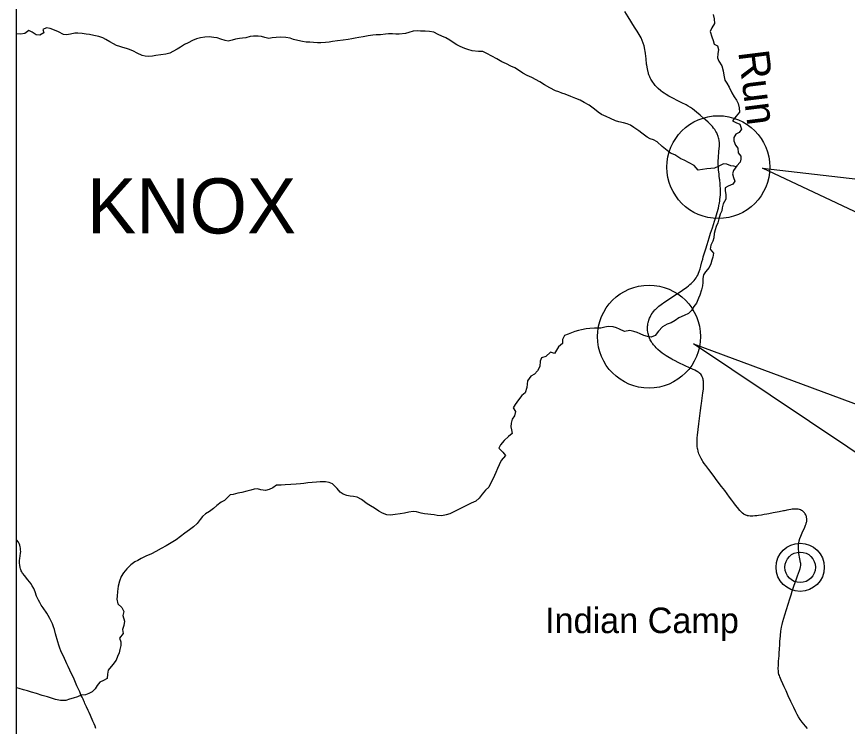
# Model space of a CAD drawing. Extents: x -12.1 to 34, y 0 to 22.
# Drawn here: x -12.146 to -9.741, y 14.162 to 16.219 of the extents above; entities that cross this region are included whole.
import ezdxf

# ---------------------------------------------------------------- set-up
doc = ezdxf.new("R2010")
doc.units = 0
for name, color, linetype in [('BR_P_Gen_Text', 7, 'Continuous'), ('Default', 7, 'Continuous'), ('GM_X_Minor_River', 7, 'Continuous'), ('GM_X_Minor_River_Text', 7, 'Continuous'), ('GM_X_State_Route', 7, 'Continuous'), ('GM_X_Township_Text', 7, 'Continuous'), ('GM_X_Unincorporated', 7, 'Continuous'), ('GM_X_Unincorporated_Location', 7, 'Continuous'), ('GM_X_Unincorporated_Text', 7, 'Continuous'), ('SH_Text', 7, 'Continuous')]:
    doc.layers.add(name, color=color, linetype=linetype)

msp = doc.modelspace()

# ---------------------------------------------------------------- linework, layer by layer
at = {"layer": 'BR_P_Gen_Text'}
for points in [[(-9.1421, 15.682), (-9.1421, 15.3818), (-9.9863, 15.7796)], [(-9.1816, 14.8981), (-9.1816, 14.5979), (-10.1862, 15.271)]]:
    msp.add_lwpolyline(points, close=True, dxfattribs=at)
at = {"layer": 'Default'}
for centre in [(-10.1144, 15.7828), (-10.3152, 15.2916)]:
    msp.add_circle(centre, 0.149, dxfattribs=at)
at = {"layer": 'GM_X_Minor_River'}
for points in [[(-10.129, 16.2246), (-10.1268, 16.2129), (-10.1256, 16.1994), (-10.1329, 16.1869), (-10.1385, 16.1762), (-10.1334, 16.1606), (-10.129, 16.1496), (-10.1268, 16.1394), (-10.1172, 16.1345), (-10.1142, 16.1238), (-10.1162, 16.1107), (-10.1172, 16.0993), (-10.1132, 16.0898), (-10.1046, 16.0763), (-10.1002, 16.0618), (-10.0987, 16.0494), (-10.0953, 16.0352), (-10.0896, 16.0257), (-10.0827, 16.0147), (-10.0755, 15.9977), (-10.0686, 15.9868), (-10.0622, 15.9773), (-10.0571, 15.967), (-10.0541, 15.9546), (-10.053, 15.9422), (-10.0628, 15.93), (-10.073, 15.9171), (-10.0633, 15.9122), (-10.0519, 15.9074), (-10.0475, 15.8925), (-10.0545, 15.8832), (-10.0641, 15.8781), (-10.0697, 15.8685), (-10.0699, 15.8592), (-10.0649, 15.8468), (-10.0584, 15.8377), (-10.0568, 15.8245), (-10.0493, 15.815), (-10.0492, 15.8058), (-10.0509, 15.7969), (-10.0608, 15.7865), (-10.0706, 15.7729), (-10.0733, 15.7636), (-10.0707, 15.7526), (-10.0664, 15.7424), (-10.0727, 15.7331), (-10.0858, 15.7273), (-10.0949, 15.7226), (-10.0949, 15.7137), (-10.0926, 15.7037), (-10.0929, 15.6895), (-10.1002, 15.6767), (-10.1036, 15.6653), (-10.1046, 15.6557), (-10.1088, 15.6464), (-10.1126, 15.6325), (-10.116, 15.6218)], [(-11.275, 16.1427), (-11.2867, 16.1443), (-11.297, 16.1449), (-11.3076, 16.1452), (-11.319, 16.1465), (-11.3325, 16.1496), (-11.3449, 16.153), (-11.3538, 16.1565), (-11.3663, 16.1581), (-11.3826, 16.1597), (-11.395, 16.1585), (-11.4064, 16.157), (-11.4159, 16.1558), (-11.428, 16.1586), (-11.4369, 16.161), (-11.4465, 16.1626), (-11.4607, 16.1625), (-11.4703, 16.1613), (-11.4823, 16.1577), (-11.4922, 16.1565), (-11.5014, 16.1553), (-11.5128, 16.1534), (-11.5223, 16.1505), (-11.534, 16.1479), (-11.5429, 16.1499), (-11.555, 16.1537), (-11.5657, 16.1572), (-11.5749, 16.1588), (-11.5884, 16.1601), (-11.6015, 16.1593), (-11.6139, 16.1574), (-11.6256, 16.1548), (-11.6372, 16.15), (-11.65, 16.1428), (-11.6598, 16.1377), (-11.6715, 16.1301), (-11.681, 16.1244), (-11.6937, 16.1178), (-11.7029, 16.1128), (-11.7146, 16.1098), (-11.7429, 16.106), (-11.7525, 16.1045), (-11.7638, 16.1036), (-11.7741, 16.1046), (-11.783, 16.1066), (-11.7969, 16.1132), (-11.808, 16.1185), (-11.819, 16.1233), (-11.8282, 16.1268), (-11.8386, 16.1295), (-11.8475, 16.1319), (-11.8567, 16.1357), (-11.8656, 16.1402), (-11.8763, 16.1462), (-11.8881, 16.1524), (-11.897, 16.157), (-11.9087, 16.1615), (-11.9223, 16.1645), (-11.9354, 16.1669), (-11.9446, 16.1682), (-11.9564, 16.1699), (-11.9688, 16.1708), (-11.978, 16.1714), (-11.9904, 16.1681), (-12.0017, 16.1662), (-12.0106, 16.1672), (-12.0249, 16.1752), (-12.0366, 16.1801), (-12.0487, 16.1842), (-12.0601, 16.1866), (-12.07, 16.1815), (-12.0674, 16.1716), (-12.0791, 16.1654), (-12.0901, 16.1664), (-12.1015, 16.1741), (-12.1111, 16.1786), (-12.1224, 16.1696), (-12.1351, 16.1684), (-12.1458, 16.1694), (-12.1463, 16.1698)], [(-10.0627, 15.7838), (-10.0696, 15.7857), (-10.0785, 15.7867), (-10.0899, 15.7912), (-10.0998, 15.7925), (-10.1147, 15.7845), (-10.126, 15.7802), (-10.1363, 15.779), (-10.148, 15.7775), (-10.16, 15.7756), (-10.1731, 15.7737), (-10.1849, 15.7871), (-10.1985, 15.7954), (-10.2138, 15.8028), (-10.2227, 15.8073), (-10.2317, 15.8125), (-10.2406, 15.8181), (-10.2534, 15.8237), (-10.2627, 15.8314), (-10.2766, 15.8423), (-10.2913, 15.856), (-10.3024, 15.8616), (-10.312, 15.865), (-10.3209, 15.8692), (-10.3355, 15.8815), (-10.3445, 15.8882), (-10.3591, 15.898), (-10.3687, 15.9039), (-10.3784, 15.9081), (-10.3894, 15.9108), (-10.4025, 15.9143), (-10.4121, 15.917), (-10.4271, 15.924), (-10.4396, 15.9299), (-10.4524, 15.9354), (-10.4624, 15.9417), (-10.4731, 15.9505), (-10.4881, 15.9621), (-10.5028, 15.9701), (-10.5145, 15.9764), (-10.527, 15.9816), (-10.5412, 15.9875), (-10.5576, 15.9938), (-10.5676, 15.9969), (-10.5765, 16.0007), (-10.5857, 16.0041), (-10.6028, 16.0125), (-10.6178, 16.0212), (-10.6314, 16.0296), (-10.6542, 16.0422), (-10.6681, 16.0485), (-10.6809, 16.0554), (-10.6934, 16.0642), (-10.7038, 16.0705), (-10.7148, 16.0757), (-10.728, 16.082), (-10.7416, 16.0882), (-10.7562, 16.0966), (-10.7704, 16.1047), (-10.7847, 16.112), (-10.7961, 16.1176), (-10.8085, 16.1178), (-10.827, 16.1197), (-10.8395, 16.1239), (-10.8484, 16.127), (-10.8619, 16.1325), (-10.8715, 16.1371), (-10.8826, 16.1441), (-10.8915, 16.1504), (-10.9036, 16.1574), (-10.9154, 16.1619), (-10.9261, 16.1671), (-10.9385, 16.1741), (-10.951, 16.1757), (-10.9634, 16.1763), (-10.9765, 16.1765), (-10.9858, 16.1775), (-10.9982, 16.1767), (-11.0106, 16.173), (-11.0205, 16.1697), (-11.0385, 16.1678), (-11.0485, 16.168), (-11.0581, 16.169), (-11.0691, 16.1692), (-11.0786, 16.1681), (-11.0928, 16.1662), (-11.1049, 16.166), (-11.1144, 16.1652), (-11.1279, 16.1633), (-11.1431, 16.1603), (-11.1552, 16.1588), (-11.1662, 16.1569), (-11.1761, 16.155), (-11.1864, 16.1528), (-11.2009, 16.1509), (-11.2175, 16.1489), (-11.2317, 16.1467), (-11.2416, 16.1451), (-11.2523, 16.144), (-11.2654, 16.1428), (-11.275, 16.1427)], [(-10.116, 15.6218), (-10.1212, 15.6107), (-10.124, 15.6015), (-10.1267, 15.5901), (-10.1277, 15.5783), (-10.1308, 15.568), (-10.1363, 15.5562), (-10.1384, 15.5448), (-10.128, 15.5336), (-10.13, 15.5222), (-10.1335, 15.5133), (-10.1362, 15.5029), (-10.1414, 15.4919), (-10.1516, 15.4797), (-10.1575, 15.4704), (-10.1596, 15.4601), (-10.1595, 15.448), (-10.1604, 15.4387), (-10.1628, 15.4277), (-10.1684, 15.412), (-10.1718, 15.4027), (-10.1777, 15.3888), (-10.1854, 15.3785), (-10.1921, 15.3677), (-10.2012, 15.3588), (-10.2132, 15.353), (-10.2288, 15.3464), (-10.2397, 15.3388), (-10.2514, 15.332), (-10.2623, 15.328), (-10.2761, 15.32), (-10.2877, 15.3078), (-10.2971, 15.2949), (-10.3092, 15.2898), (-10.3198, 15.2922), (-10.3305, 15.2953), (-10.3405, 15.2995), (-10.3497, 15.3037), (-10.3593, 15.3068), (-10.3711, 15.3095), (-10.3859, 15.3065), (-10.4006, 15.3131), (-10.4095, 15.3169), (-10.4194, 15.32), (-10.4333, 15.3206), (-10.4432, 15.3191), (-10.4545, 15.3165), (-10.4733, 15.3163), (-10.4861, 15.3155), (-10.4971, 15.3139), (-10.5102, 15.3113), (-10.5194, 15.3091), (-10.53, 15.3062), (-10.5399, 15.3029), (-10.5494, 15.2992), (-10.56, 15.2945), (-10.5653, 15.2831), (-10.5652, 15.2714), (-10.5768, 15.2616), (-10.589, 15.2423), (-10.6004, 15.2465), (-10.6138, 15.2339), (-10.6269, 15.2306), (-10.6307, 15.221), (-10.6312, 15.205), (-10.6379, 15.1921), (-10.6467, 15.1831), (-10.6569, 15.1767), (-10.667, 15.1634), (-10.668, 15.1535), (-10.669, 15.1442), (-10.6742, 15.1292), (-10.6837, 15.121), (-10.6931, 15.1081), (-10.703, 15.0948), (-10.7082, 15.0855), (-10.7017, 15.0749), (-10.7048, 15.0625), (-10.7114, 15.0525), (-10.7145, 15.0404), (-10.7148, 15.0304), (-10.7133, 15.0212), (-10.7118, 15.0112), (-10.722, 15.0023), (-10.735, 14.9904), (-10.7448, 14.9782), (-10.7497, 14.9689), (-10.7382, 14.9566), (-10.7307, 14.9475), (-10.7433, 14.9328), (-10.7492, 14.9206), (-10.7534, 14.9099), (-10.7586, 14.8982), (-10.7666, 14.881), (-10.7732, 14.8682), (-10.7788, 14.8557), (-10.7887, 14.8463), (-10.7981, 14.8349), (-10.8069, 14.8234), (-10.8164, 14.8148), (-10.8302, 14.8086)], [(-10.8302, 14.8086), (-10.8397, 14.8046), (-10.8588, 14.7948), (-10.8711, 14.7887), (-10.8821, 14.7825), (-10.892, 14.7778), (-10.9029, 14.7748), (-10.9153, 14.7726), (-10.9285, 14.7735), (-10.9377, 14.7749), (-10.9466, 14.7762), (-10.9555, 14.7775), (-10.9654, 14.7785), (-10.9747, 14.7805), (-10.9882, 14.784), (-10.9981, 14.7846), (-11.0109, 14.7827), (-11.0233, 14.7804), (-11.036, 14.7778), (-11.0502, 14.7762), (-11.064, 14.7747), (-11.0743, 14.7753), (-11.0864, 14.7805), (-11.0978, 14.7857), (-11.1096, 14.7941), (-11.1217, 14.8011), (-11.1317, 14.8074), (-11.1478, 14.82), (-11.1599, 14.8267), (-11.1709, 14.8287), (-11.1809, 14.8293), (-11.1905, 14.8313), (-11.2008, 14.8348), (-11.2097, 14.8411), (-11.2183, 14.8517), (-11.2312, 14.8647), (-11.2409, 14.8685), (-11.2515, 14.8709), (-11.2678, 14.8711), (-11.2781, 14.8703), (-11.2909, 14.8694), (-11.3033, 14.8675), (-11.315, 14.8656), (-11.3242, 14.8648), (-11.337, 14.8643), (-11.3519, 14.8635), (-11.3689, 14.8622), (-11.3799, 14.8614), (-11.3937, 14.8609), (-11.4046, 14.8537), (-11.4152, 14.8483), (-11.4258, 14.8457), (-11.4393, 14.8477), (-11.4493, 14.8501), (-11.4585, 14.8493), (-11.4684, 14.847), (-11.4794, 14.8437), (-11.4943, 14.84), (-11.5059, 14.8378), (-11.5194, 14.8344), (-11.5275, 14.8331)], [(-11.5275, 14.8331), (-11.5335, 14.8275), (-11.5441, 14.8168), (-11.5536, 14.8117), (-11.5663, 14.802), (-11.5761, 14.7937), (-11.5881, 14.7847), (-11.599, 14.7782), (-11.6082, 14.7703), (-11.6149, 14.7613), (-11.6233, 14.7499), (-11.6342, 14.7402), (-11.6462, 14.7319), (-11.6588, 14.7222), (-11.6846, 14.7027), (-11.6987, 14.694), (-11.7128, 14.6857), (-11.728, 14.6778), (-11.7431, 14.6691), (-11.7558, 14.6622), (-11.7721, 14.6556), (-11.7852, 14.6491), (-11.795, 14.6433), (-11.8042, 14.6386), (-11.8159, 14.6303), (-11.8271, 14.6192), (-11.8373, 14.607), (-11.8439, 14.5963), (-11.8488, 14.5831), (-11.8522, 14.5681), (-11.8538, 14.5532), (-11.8555, 14.5397), (-11.8557, 14.5304), (-11.8531, 14.5169), (-11.842, 14.5064), (-11.8362, 14.4947), (-11.8383, 14.484), (-11.8342, 14.467), (-11.8362, 14.4546), (-11.84, 14.4425), (-11.8378, 14.4311), (-11.8483, 14.4178), (-11.8443, 14.4076), (-11.8442, 14.3969), (-11.8473, 14.3852), (-11.8493, 14.3756), (-11.8538, 14.3652), (-11.8576, 14.3538), (-11.8675, 14.342), (-11.8815, 14.3251), (-11.8832, 14.3134), (-11.8838, 14.3013), (-11.8951, 14.2948), (-11.9057, 14.2908), (-11.9134, 14.2804), (-11.9186, 14.2715), (-11.9274, 14.2621), (-11.9373, 14.2574), (-11.9468, 14.2541), (-11.9596, 14.2522), (-11.9705, 14.2482), (-11.9822, 14.2438), (-11.9928, 14.2409), (-12.0038, 14.2375), (-12.0194, 14.2374), (-12.0336, 14.2404), (-12.0571, 14.248), (-12.0724, 14.2521), (-12.0884, 14.2577), (-12.103, 14.2611), (-12.1147, 14.2649), (-12.1268, 14.2686), (-12.1393, 14.2724), (-12.1463, 14.2737)]]:
    msp.add_lwpolyline(points, dxfattribs=at)
at = {"layer": 'GM_X_State_Route'}
for points in [[(-10.3187, 15.3269), (-10.3184, 15.3289), (-10.3178, 15.3322), (-10.3171, 15.3349), (-10.3157, 15.3393), (-10.3133, 15.3456), (-10.3122, 15.3483), (-10.31, 15.3528), (-10.3088, 15.3549), (-10.3063, 15.3587), (-10.305, 15.3606), (-10.3012, 15.3655), (-10.2979, 15.3691), (-10.2964, 15.3707), (-10.2926, 15.3744), (-10.2867, 15.3796), (-10.2797, 15.385), (-10.269, 15.3923), (-10.256, 15.401), (-10.2406, 15.4113), (-10.228, 15.4196), (-10.2179, 15.4265), (-10.2061, 15.4349), (-10.2006, 15.4392), (-10.1966, 15.4425), (-10.1927, 15.4459), (-10.1894, 15.449), (-10.1873, 15.4511), (-10.1846, 15.4541), (-10.1814, 15.4581), (-10.1786, 15.462), (-10.1764, 15.4657), (-10.1741, 15.47), (-10.1719, 15.4751), (-10.1698, 15.4808), (-10.1675, 15.488), (-10.1653, 15.4957), (-10.162, 15.508), (-10.1598, 15.5159), (-10.1579, 15.5229), (-10.157, 15.526), (-10.1555, 15.5312), (-10.1508, 15.5464), (-10.147, 15.5588), (-10.1442, 15.568), (-10.1413, 15.5775), (-10.1391, 15.5845), (-10.1369, 15.5914), (-10.1317, 15.6073), (-10.1254, 15.6264), (-10.1217, 15.6381), (-10.1178, 15.651), (-10.1141, 15.6643), (-10.1127, 15.671), (-10.1116, 15.676), (-10.1112, 15.6785), (-10.1102, 15.685), (-10.1098, 15.6886), (-10.1091, 15.6958), (-10.1086, 15.7027), (-10.1084, 15.7103), (-10.1085, 15.7166), (-10.1085, 15.7221), (-10.1088, 15.7281), (-10.1092, 15.7339), (-10.1096, 15.7383), (-10.11, 15.7422), (-10.1104, 15.7457), (-10.1108, 15.7491), (-10.1118, 15.7575), (-10.1125, 15.7628), (-10.1137, 15.7745), (-10.1144, 15.7828), (-10.1146, 15.7905), (-10.1148, 15.8003), (-10.1142, 15.8104), (-10.1126, 15.8282), (-10.1117, 15.8368), (-10.1114, 15.8434), (-10.1113, 15.8495), (-10.1114, 15.8524), (-10.1123, 15.8605), (-10.1131, 15.8644), (-10.1138, 15.8673), (-10.1151, 15.8717), (-10.1158, 15.874), (-10.1169, 15.8767), (-10.1191, 15.8817), (-10.1214, 15.8861), (-10.125, 15.8918), (-10.1281, 15.8961), (-10.1318, 15.9006), (-10.1373, 15.9064), (-10.144, 15.9128), (-10.1513, 15.9195), (-10.1562, 15.9238), (-10.1668, 15.9332), (-10.1774, 15.9422), (-10.1831, 15.947), (-10.1895, 15.9519), (-10.1954, 15.9559), (-10.2018, 15.9597), (-10.208, 15.9631), (-10.2198, 15.9692), (-10.2336, 15.9763), (-10.2443, 15.982), (-10.2576, 15.9888), (-10.2657, 15.9932), (-10.2713, 15.9967), (-10.2765, 16.0003), (-10.2811, 16.0039), (-10.2883, 16.0104), (-10.2928, 16.0146), (-10.2972, 16.0195), (-10.2997, 16.0225), (-10.3015, 16.025), (-10.3043, 16.0288), (-10.3061, 16.0315), (-10.3096, 16.0374), (-10.3116, 16.0413), (-10.313, 16.0444), (-10.3146, 16.048), (-10.3155, 16.0507), (-10.3162, 16.0528), (-10.3171, 16.0559), (-10.3176, 16.0584), (-10.3196, 16.0675), (-10.3215, 16.0778), (-10.322, 16.0815), (-10.3238, 16.0964), (-10.3255, 16.1116), (-10.3263, 16.1186), (-10.327, 16.1228), (-10.3283, 16.129), (-10.3296, 16.1346), (-10.3319, 16.1423), (-10.3346, 16.1496), (-10.3381, 16.1573), (-10.3434, 16.1673), (-10.3493, 16.1768), (-10.3552, 16.1859), (-10.3618, 16.1961), (-10.3681, 16.2062), (-10.3758, 16.2181), (-10.3856, 16.2338)], [(-9.8565, 14.1561), (-9.8625, 14.1625), (-9.8673, 14.1684), (-9.8719, 14.1745), (-9.8771, 14.1822), (-9.882, 14.1902), (-9.8858, 14.1968), (-9.8899, 14.2045), (-9.8959, 14.2165), (-9.9045, 14.2343), (-9.9119, 14.2508), (-9.9183, 14.2651), (-9.9235, 14.2768), (-9.9273, 14.2854), (-9.9322, 14.2966), (-9.9361, 14.3057), (-9.9378, 14.3098), (-9.9388, 14.3127), (-9.94, 14.3174), (-9.9404, 14.3201), (-9.9406, 14.3222), (-9.9409, 14.3299), (-9.9405, 14.3397), (-9.9398, 14.3513), (-9.9387, 14.367), (-9.938, 14.3775), (-9.9377, 14.3838), (-9.9367, 14.4013), (-9.9361, 14.4106), (-9.9358, 14.4147), (-9.9347, 14.4251), (-9.9331, 14.4385), (-9.9313, 14.45), (-9.9299, 14.4577), (-9.9276, 14.4664), (-9.922, 14.4856), (-9.9077, 14.5316), (-9.904, 14.5435), (-9.9006, 14.5539), (-9.8958, 14.5684), (-9.8883, 14.59), (-9.8855, 14.5981), (-9.8795, 14.6139), (-9.8776, 14.6199), (-9.8766, 14.6244), (-9.876, 14.6282), (-9.8759, 14.6316), (-9.876, 14.6339), (-9.8765, 14.6375), (-9.8783, 14.6476), (-9.8811, 14.6631), (-9.8818, 14.6683), (-9.8824, 14.6753), (-9.8827, 14.6825), (-9.8824, 14.6874), (-9.8822, 14.6898), (-9.8817, 14.6933), (-9.8804, 14.6999), (-9.8783, 14.7069), (-9.8756, 14.7139), (-9.8716, 14.7233), (-9.8638, 14.7397), (-9.8616, 14.7454), (-9.8603, 14.7492), (-9.8598, 14.7508), (-9.8589, 14.7543), (-9.8586, 14.756), (-9.8583, 14.7587), (-9.8583, 14.7603), (-9.8584, 14.7642), (-9.8587, 14.767), (-9.8591, 14.7689), (-9.8595, 14.7704), (-9.8601, 14.7724), (-9.8613, 14.7752), (-9.8629, 14.7781), (-9.8637, 14.7793), (-9.8649, 14.781), (-9.8664, 14.7828), (-9.8682, 14.7844), (-9.87, 14.7859), (-9.871, 14.7866), (-9.8724, 14.7874), (-9.8737, 14.7881), (-9.8765, 14.7894), (-9.8797, 14.7905), (-9.8837, 14.7914), (-9.8877, 14.7919), (-9.8922, 14.792), (-9.8961, 14.7918), (-9.9007, 14.7912), (-9.9047, 14.7905), (-9.9103, 14.7896), (-9.9158, 14.7886), (-9.9189, 14.7879), (-9.9224, 14.7873), (-9.9256, 14.7867), (-9.9297, 14.786), (-9.9344, 14.7851), (-9.9385, 14.7842), (-9.944, 14.7832), (-9.9559, 14.7808), (-9.968, 14.7786), (-9.9744, 14.7774), (-9.9821, 14.776), (-9.9898, 14.7747), (-9.9979, 14.7733), (-10.0033, 14.7725), (-10.0084, 14.7719), (-10.0146, 14.7714), (-10.0185, 14.7713), (-10.0226, 14.7715), (-10.027, 14.7721), (-10.03, 14.7727), (-10.0313, 14.773), (-10.0324, 14.7734), (-10.0344, 14.7742), (-10.0363, 14.775), (-10.0392, 14.7766), (-10.0406, 14.7774), (-10.0444, 14.78), (-10.0472, 14.7825), (-10.0487, 14.7839), (-10.0523, 14.7877), (-10.0592, 14.7962), (-10.0644, 14.803), (-10.0696, 14.8099), (-10.0726, 14.8139), (-10.0754, 14.8176), (-10.0821, 14.8264), (-10.0961, 14.8456), (-10.1049, 14.857), (-10.1177, 14.8742), (-10.1296, 14.8898), (-10.1421, 14.9063), (-10.1509, 14.9181), (-10.1552, 14.9242), (-10.1589, 14.9294), (-10.1604, 14.9318), (-10.1644, 14.9387), (-10.1654, 14.9404), (-10.1663, 14.9422), (-10.1671, 14.9438), (-10.1681, 14.9462), (-10.169, 14.9482), (-10.1705, 14.9521), (-10.1717, 14.9554), (-10.1725, 14.9581), (-10.1733, 14.961), (-10.1741, 14.9645), (-10.1747, 14.9679), (-10.1754, 14.973), (-10.1759, 14.9775), (-10.176, 14.9804), (-10.1761, 14.9842), (-10.1756, 14.9924), (-10.1753, 14.9981), (-10.1747, 15.0057), (-10.1709, 15.0385), (-10.1658, 15.078), (-10.1638, 15.0919), (-10.163, 15.0976), (-10.1611, 15.113), (-10.159, 15.1284), (-10.1576, 15.1398), (-10.1571, 15.1493), (-10.157, 15.1519), (-10.1572, 15.1571), (-10.1576, 15.1621), (-10.158, 15.165), (-10.1586, 15.1685), (-10.1593, 15.1711), (-10.1601, 15.1733), (-10.161, 15.1754), (-10.162, 15.1776), (-10.1634, 15.1798), (-10.1655, 15.1825), (-10.1676, 15.1847), (-10.169, 15.186), (-10.1703, 15.187), (-10.1725, 15.1885), (-10.176, 15.1907), (-10.1781, 15.1919), (-10.1824, 15.194), (-10.1961, 15.2004), (-10.2121, 15.2076), (-10.2288, 15.2158), (-10.2416, 15.2223), (-10.2466, 15.2248), (-10.2489, 15.2261), (-10.2603, 15.2326), (-10.2654, 15.2358), (-10.2716, 15.24), (-10.2769, 15.2437), (-10.2833, 15.2488), (-10.2895, 15.2542), (-10.2941, 15.2587), (-10.2977, 15.2626), (-10.301, 15.2665), (-10.3024, 15.2682), (-10.3043, 15.2708), (-10.3057, 15.2728), (-10.3083, 15.2767), (-10.3098, 15.2792), (-10.3115, 15.2824), (-10.3134, 15.2867), (-10.3144, 15.2896), (-10.3152, 15.2916), (-10.3166, 15.296), (-10.3171, 15.298), (-10.3178, 15.301), (-10.3185, 15.3045), (-10.3191, 15.3099), (-10.3194, 15.3161), (-10.3193, 15.3217), (-10.319, 15.3247), (-10.3187, 15.3269)], [(-11.9169, 14.1565), (-11.919, 14.1632), (-11.9215, 14.1695), (-11.9253, 14.1777), (-11.9326, 14.1938), (-11.9366, 14.2023), (-11.9391, 14.2084), (-11.9436, 14.2184), (-11.9458, 14.2231), (-11.9484, 14.2286), (-11.9501, 14.2326), (-11.9506, 14.2336), (-11.954, 14.2409), (-11.9566, 14.2467), (-11.959, 14.2519), (-11.9611, 14.2567), (-11.9636, 14.2619), (-11.9716, 14.28), (-11.98, 14.2986), (-11.992, 14.3251), (-11.9969, 14.3357), (-12.0008, 14.3435), (-12.011, 14.3655), (-12.0143, 14.3728), (-12.0179, 14.3811), (-12.021, 14.389), (-12.024, 14.3973), (-12.0273, 14.4077), (-12.0335, 14.4308), (-12.0369, 14.4427), (-12.0395, 14.451), (-12.0424, 14.4592), (-12.0459, 14.4668), (-12.0501, 14.475), (-12.0546, 14.4833), (-12.059, 14.4905), (-12.0698, 14.5055), (-12.0751, 14.5134), (-12.0793, 14.5208), (-12.0829, 14.5278), (-12.0857, 14.5337), (-12.0883, 14.54), (-12.0929, 14.5525), (-12.0969, 14.5618), (-12.1009, 14.5696), (-12.1049, 14.576), (-12.1078, 14.5797), (-12.1148, 14.5881), (-12.1229, 14.5984), (-12.1288, 14.606), (-12.1312, 14.61), (-12.1329, 14.6134), (-12.135, 14.6189), (-12.1362, 14.623), (-12.1374, 14.6293), (-12.1379, 14.6356), (-12.1376, 14.6425), (-12.1367, 14.6487), (-12.1356, 14.6564), (-12.1348, 14.6644), (-12.1345, 14.6691), (-12.1347, 14.6731), (-12.1351, 14.6785), (-12.136, 14.6827), (-12.1373, 14.6871), (-12.1392, 14.6919), (-12.1413, 14.6959), (-12.1453, 14.7022), (-12.1463, 14.7033)]]:
    msp.add_lwpolyline(points, dxfattribs=at)
at = {"layer": 'GM_X_Unincorporated'}
for radius in [0.0698, 0.0442]:
    msp.add_circle((-9.8775, 14.6232), radius, dxfattribs=at)
at = {"layer": 'GM_X_Unincorporated_Location'}
msp.add_line((-9.8775, 14.6232), (-9.8775, 14.6232), dxfattribs=at)
at = {"layer": 'SH_Text'}
msp.add_lwpolyline([(-12.1463, 20.3063), (-4.4383, 20.3063), (-4.4383, 10.9773), (-12.1463, 10.9773)], close=True, dxfattribs=at)

# ---------------------------------------------------------------- texts
at = {"layer": 'GM_X_Minor_River_Text'}
msp.add_text('Run', height=0.08877, rotation=277.0886, dxfattribs=at).set_placement((-10.0569, 16.1168))
at = {"layer": 'GM_X_Township_Text'}
msp.add_text('KNOX', height=0.1598, rotation=0, dxfattribs=at).set_placement((-11.9423, 15.5905))
at = {"layer": 'GM_X_Unincorporated_Text'}
msp.add_text('Indian Camp', height=0.074041, rotation=0, dxfattribs=at).set_placement((-10.6163, 14.4324))

doc.saveas('drawing.dxf')
